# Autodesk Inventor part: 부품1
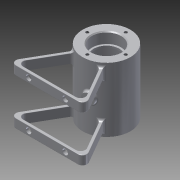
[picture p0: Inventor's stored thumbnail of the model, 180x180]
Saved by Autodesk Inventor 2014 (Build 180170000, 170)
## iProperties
Created: 2016-03
Part Number: 부품1
Material: 알루미늄 6061
Document SubType Name: Modeling
Designer: 406-017
Density: 2.71 g/cm^3
Appearance: 알루미늄 - 평지
Mass: 212.639 g
Surface Area: 335.819 cm^2
Volume: 78.4645 cm^3
Author: 406-017
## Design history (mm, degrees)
sketch "스케치1"
  geometry: C1 r 26 at (0, 0); 1 further point
  constraints: 1 centre point, 1 coincident
  dimensions: "d0" = 52 diameter of C1
extrude "돌출1" new body sketch "스케치1" distance "d1" = 70; taper "d2" = 0 deg
sketch "스케치2"
  geometry: L1 (16, 0)-(16, -12); L2 (16, -12)-(14, -12); L3 (14, -12)-(14, -14); L4 (14, -14)-(21, -14); L5 (21, -14)-(21, -56); L6 (21, -56)-(14, -56); L7 (14, -56)-(14, -58); L8 (14, -58)-(16, -58); L9 (16, -58)-(16, -70); L10 (16, -70)-(0, -70); L11 (0, -70)-(0, 0); L12 (0, 0)-(16, 0)
  constraints: 24 end point, 9 parallel, 1 collinear, 1 perpendicular, 1 vertical
  dimensions: "d3" = 32 diameter of L1 L11; "d4" = 42 diameter of L5 L11; "d5" = 32 diameter of L9 L11; "d6" = 2 distance of L2.end L3.end; "d7" = 2 distance of L6.end L7.end; "d8" = 12 distance of L8.end L9.end; "d9" = 42 distance of L4.end L5.end; "d10" = 12 distance of L1.start L1.end; "d11" = 28 diameter of L3 L11; "d12" = 28 diameter of L7 L11
node "작업 평면1"
sketch "스케치3"
  geometry: L1 (-26, -70)-(26, -70) reference; C1 r 5 at (0, -35); 1 further point
  constraints: 1 centre point, 1 vertical alignment
  dimensions: "d15" = 10 diameter of C1; "d16" = 35 distance from line of L1 C1.centre
extrude "돌출2" join sketch "스케치3" distance "d17" = 5; taper "d18" = 0 deg
node "작업 평면2"
sketch "스케치4"
  geometry: L1 (0, 0)-(0, -26.03); L2 (0, 0)-(7.506, -28.012)
  constraints: 4 end point, 1 vertical
  dimensions: "d20" = 15 deg angle of L1 L2; "d21" = 29 distance of L1.start L2.end; "d22" = 26.02996 distance of L1.start L1.end
node "작업 평면3"
sketch "스케치5"
  geometry: C1 r 6 at (0, 0); 1 further point
  constraints: 1 centre point, 1 vertical alignment
  dimensions: "d23" = 12 diameter of C1; "d24" = 35 distance of point (0, 35) C1.centre
extrude "돌출3" join sketch "스케치5" distance "d25" = 5; taper "d26" = 0 deg
node "작업 평면4"
sketch "스케치6"
  geometry: L1 (-16.613, -20)-(-42.594, -65); L2 (-42.594, -65)-(42.594, -65); L3 (42.594, -65)-(16.613, -20); L4 (16.613, -20)-(-16.613, -20); L5 (0, 0)-(0, -65); L6 (13.677, -20.913)-(37.398, -62); L7 (37.398, -62)-(-37.398, -62); L8 (-37.398, -62)-(-13.677, -20.913); L9 (-13.677, -20.913)-(13.677, -20.913); 2 further points
  constraints: 18 end point, 2 midpoint, 2 parallel, 1 horizontal, 1 perpendicular, 1 point on line, 2 other
  dimensions: "d28" = 30 deg angle of L5 L1; "d29" = 30 deg angle of L5 L3; "d32" = 65 distance from line of L2 L5.start; "d33" = 45 distance from line of L2 L3.end; "d34" = 3 distance between parallel lines of L2 L7; "d35" = 3 distance between parallel lines of L1 L8; "d36" = 3 distance between parallel lines of L6 L3; "d37" = 0.91346 distance between parallel lines of L4 L9
extrude "돌출4" join sketch "스케치6" distance "d38" = 10; taper "d39" = 0 deg
node "작업 평면5"
sketch "스케치7"
  geometry: C1 r 5 at (0, 0) reference; 2 further points
  constraints: 1 coincident
hole "구멍1" sketch "스케치7" at (0, 0) diameter "d41" = 5.188; stored, may be unused: countersink angle "d45" = 90 deg, drill point angle "d47" = 118 deg; dims "d42" = 10, "d43" = 4, "d44" = 2, "d46" = 11
revolve "회전2" stored, may be unused: angle "d48" = 90 deg
sketch "스케치10"
  geometry: L1 (0, 0)-(0, 21); C1 r 16 at (0, 0) reference; C2 r 26 at (0, 0) reference
  constraints: 2 end point, 1 vertical
  dimensions: "d49" = 21 distance of L1.end C1.centre
hole "구멍2" sketch "스케치10" at (0, 21) diameter "d50" = 3.242; stored, may be unused: countersink angle "d54" = 90 deg, drill point angle "d56" = 118 deg; dims "d51" = 8, "d52" = 4, "d53" = 2, "d55" = 10
sketch "스케치11"
  geometry: L1 (0, 10)-(74.796, 10) reference; C1 r 3 at (17.398, 5); C2 r 3 at (57.398, 5); 1 further point
  constraints: 2 centre point
  dimensions: "d60" = 6 diameter of C1; "d61" = 6 diameter of C2; "d62" = 5 distance from line of L1 C2.centre; "d63" = 20 horizontal distance of point (37.398, -5) C2.centre; "d64" = 40 distance of C2.centre C1.centre; "d65" = 20 horizontal distance of C1.centre point (37.398, -5)
extrude "돌출5" cut sketch "스케치11" distance "d66" = 20; taper "d67" = 0 deg
sketch "스케치12"
  geometry: C1 r 6 at (0, 0) reference; 2 further points
  constraints: 1 coincident
hole "구멍3" sketch "스케치12" at (0, 0) diameter "d68" = 5.188; stored, may be unused: countersink angle "d72" = 90 deg, drill point angle "d74" = 118 deg; dims "d69" = 8, "d70" = 4, "d71" = 2, "d73" = 10
fillet "모깎기2" dims "d76" = 0.3
node "작업 평면7"
  node "작업 평면6"
sketch "스케치15"
  geometry: L1 (-26, -70)-(26, -70) reference; 2 further points
  constraints: 1 vertical alignment, 1 other
  dimensions: "d79" = 35 distance from line of L1 point (0, -35)
feature "엠보싱1" sketch "스케치15" dims "d0" = 52, "d80" = 0.5, "d81" = 0
chamfer "모따기1" distance "d82" = 1; stored, may be unused: second distance "d83" = 2, angle "d84" = 45 deg
fillet "모깎기4" dims "d85" = 2
fillet "모깎기5" dims "d86" = 3
fillet "모깎기6" dims "d87" = 5
fillet "모깎기8" dims "d89" = 5
fillet "모깎기9" dims "d90" = 3
fillet "모깎기10" dims "d91" = 3
fillet "모깎기11" dims "d92" = 0.5
fillet "모깎기12" dims "d93" = 3
node "솔리드1"
mirror "대칭1"
pattern_circular "원형 패턴1" dims angle "d58" = 360 deg
mirror "대칭2"
mirror "대칭3"
other parameters: "d14" = 29, "d19" = -35, "d27" = -5, "d40" = -35, "d78" = -52
